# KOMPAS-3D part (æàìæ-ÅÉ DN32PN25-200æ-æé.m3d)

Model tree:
1. Объединить компоненты:2  (labels: СЕНС-ПР DN32PN25-200С)
2. Эскиз:1
3. Операция выдавливания:1
     Расстояние 1 = 14
4. Фаска:1
     Угол = 45; Длина 1 = 2; Длина 2 = 2

Referenced files in D:\Савин\!СЕНСОР\3D для заказчика\!Новый перечень\СЕНС-ПР\2. СЕНС-ПР-200С\DN32\: СЕНС-ПР DN32PN25-200С.a3d
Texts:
  СЕНС-ПР DN32PN25-200С-СВ
  ООО НПП Сенсор
  СЕНС-ПР DN32PN25-200С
